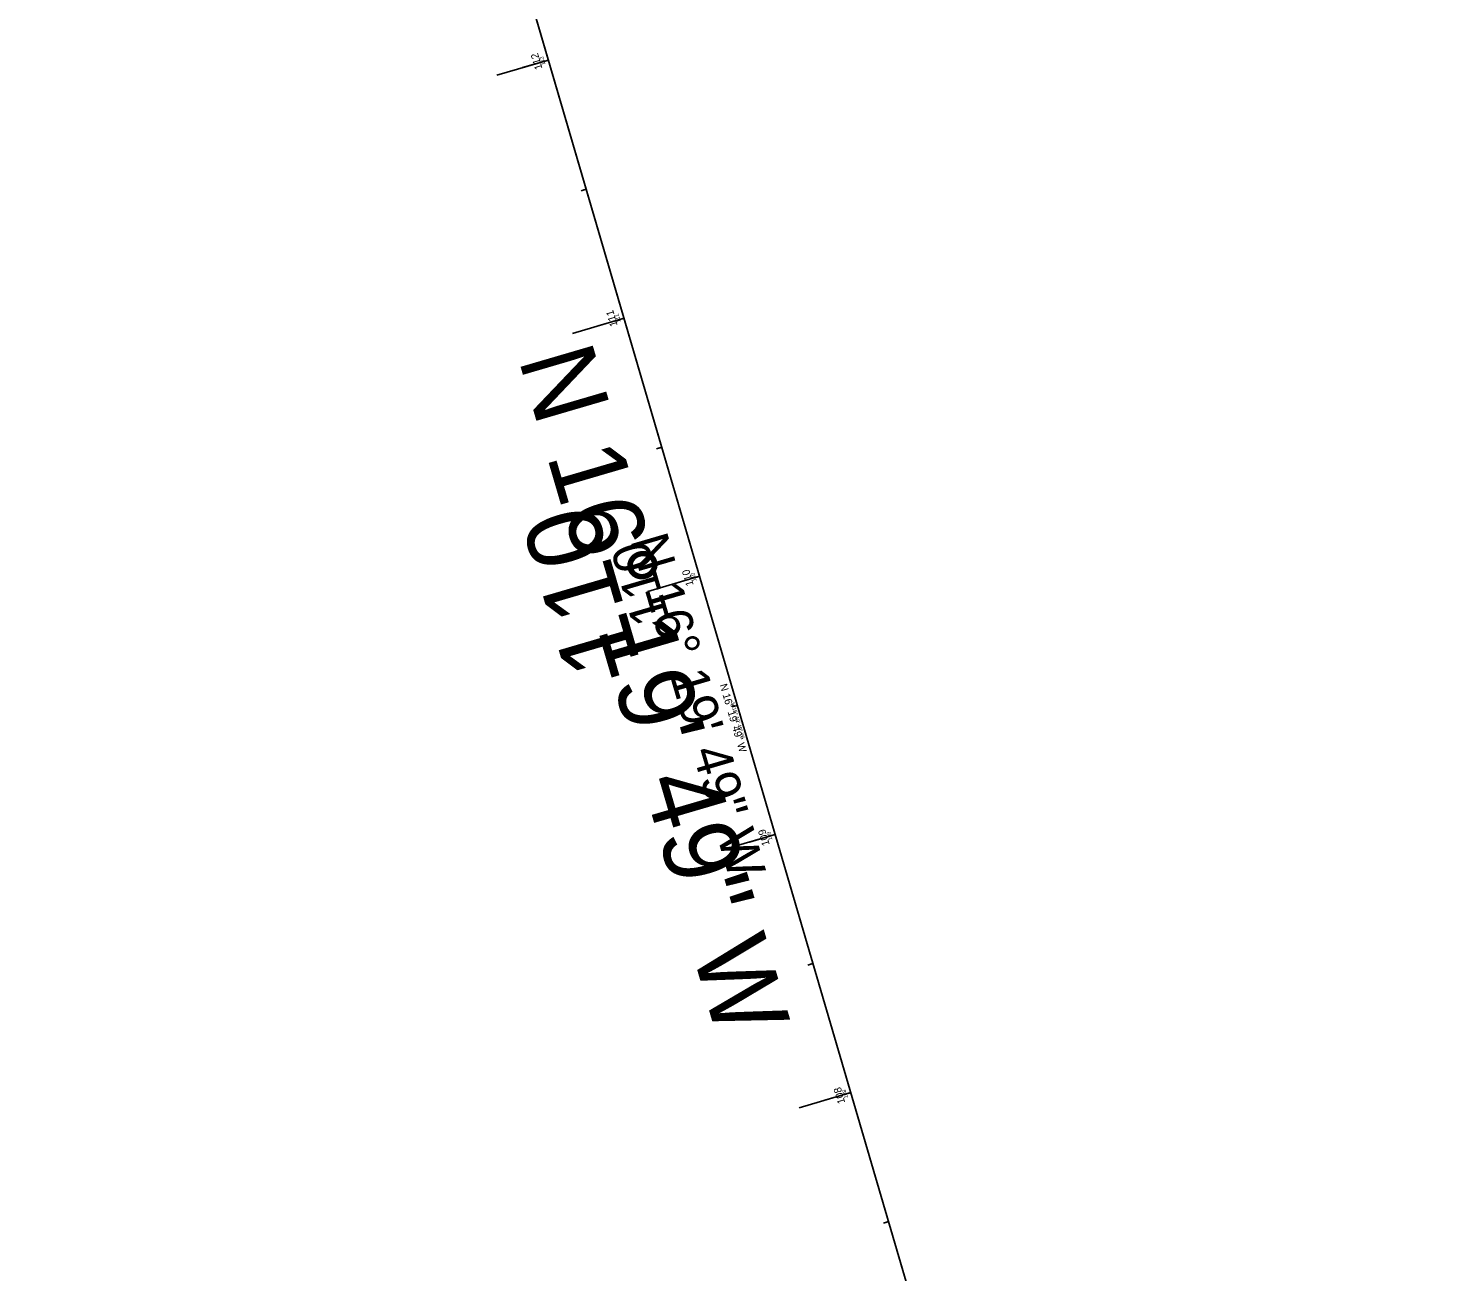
# Model space of a CAD drawing. Extents: x 1794716 to 1797874, y 325521 to 329174.
# Drawn here: x 1796270 to 1796801, y 326414 to 326876 of the extents above; entities that cross this region are included whole.
import ezdxf

# ---------------------------------------------------------------- set-up
doc = ezdxf.new("R2010")
doc.units = 0
for name, color, linetype in [('GE_P_CL_10', 7, 'Continuous'), ('GE_P_CL_100', 7, 'Continuous'), ('GE_P_CL_20', 7, 'Continuous'), ('GE_P_CL_200', 7, 'Continuous'), ('RW_X_CL_20', 7, 'Continuous')]:
    doc.layers.add(name, color=color, linetype=linetype)

msp = doc.modelspace()

# ---------------------------------------------------------------- linework, layer by layer
at = {"layer": 'GE_P_CL_10'}
for p, q in [((1796800.73, 325712.87), (1796269.93, 327524.51)), ((1796463.32, 326864.46), (1796462.36, 326864.18)), ((1796477.38, 326816.48), (1796476.42, 326816.19)), ((1796491.44, 326768.49), (1796490.48, 326768.21)), ((1796505.5, 326720.51), (1796504.54, 326720.23)), ((1796519.56, 326672.53), (1796518.6, 326672.25)), ((1796533.61, 326624.54), (1796532.66, 326624.26)), ((1796547.67, 326576.56), (1796546.71, 326576.28)), ((1796561.73, 326528.58), (1796560.77, 326528.3)), ((1796575.79, 326480.6), (1796574.83, 326480.31)), ((1796589.85, 326432.61), (1796588.89, 326432.33))]:
    msp.add_line(p, q, dxfattribs=at)
at = {"layer": 'GE_P_CL_100'}
for p, q in [((1796800.73, 325712.87), (1796269.93, 327524.51)), ((1796463.32, 326864.46), (1796453.72, 326861.65)), ((1796491.44, 326768.49), (1796481.84, 326765.68)), ((1796519.56, 326672.53), (1796509.96, 326669.72)), ((1796547.67, 326576.56), (1796538.08, 326573.75)), ((1796575.79, 326480.6), (1796566.19, 326477.78))]:
    msp.add_line(p, q, dxfattribs=at)
at = {"layer": 'GE_P_CL_20'}
for p, q in [((1796800.73, 325712.87), (1796269.93, 327524.51)), ((1796463.32, 326864.46), (1796461.4, 326863.9)), ((1796477.38, 326816.48), (1796475.46, 326815.91)), ((1796491.44, 326768.49), (1796489.52, 326767.93)), ((1796505.5, 326720.51), (1796503.58, 326719.95)), ((1796519.56, 326672.53), (1796517.64, 326671.96)), ((1796533.61, 326624.54), (1796531.7, 326623.98)), ((1796547.67, 326576.56), (1796545.75, 326576)), ((1796561.73, 326528.58), (1796559.81, 326528.02)), ((1796575.79, 326480.6), (1796573.87, 326480.03)), ((1796589.85, 326432.61), (1796587.93, 326432.05))]:
    msp.add_line(p, q, dxfattribs=at)
at = {"layer": 'GE_P_CL_200'}
for p, q in [((1796800.73, 325712.87), (1796269.93, 327524.51)), ((1796463.32, 326864.46), (1796444.13, 326858.83)), ((1796491.44, 326768.49), (1796472.25, 326762.87)), ((1796519.56, 326672.53), (1796500.36, 326666.9)), ((1796547.67, 326576.56), (1796528.48, 326570.94)), ((1796575.79, 326480.6), (1796556.6, 326474.97))]:
    msp.add_line(p, q, dxfattribs=at)
at = {"layer": 'RW_X_CL_20'}
msp.add_lwpolyline([(1796800.73, 325712.87), (1796269.93, 327524.51)], dxfattribs=at)

# ---------------------------------------------------------------- texts
at = {"layer": 'GE_P_CL_10'}
for s, rotation, p in [('112', 106.3303, (1796462.21, 326862.9)), ('111', 106.3303, (1796490.27, 326767.16)), ('110', 106.3303, (1796518.46, 326670.94)), ('N 16%%d 19\' 49" W', 286.3303, (1796531.17, 326625.42)), ('109', 106.3303, (1796546.66, 326574.67)), ('108', 106.3303, (1796574.78, 326478.72))]:
    msp.add_text(s, height=1.4, rotation=rotation, dxfattribs=at).set_placement(p)
at = {"layer": 'GE_P_CL_100'}
for s, rotation, p in [('N 16%%d 19\' 49" W', 286.3303, (1796493.72, 326686.03)), ('110', 106.3303, (1796508.58, 326656.63))]:
    msp.add_text(s, height=14, rotation=rotation, dxfattribs=at).set_placement(p)
at = {"layer": 'GE_P_CL_20'}
for s, rotation, p in [('112', 106.3303, (1796461.11, 326861.34)), ('111', 106.3303, (1796489.09, 326765.82)), ('110', 106.3303, (1796517.36, 326669.35)), ('N 16%%d 19\' 49" W', 286.3303, (1796527.01, 326632.16)), ('109', 106.3303, (1796545.66, 326572.78)), ('108', 106.3303, (1796573.76, 326476.85))]:
    msp.add_text(s, height=2.8, rotation=rotation, dxfattribs=at).set_placement(p)
at = {"layer": 'GE_P_CL_200'}
for s, rotation, p in [('N 16%%d 19\' 49" W', 286.3303, (1796452.1, 326753.37)), ('110', 106.3303, (1796497.61, 326640.73))]:
    msp.add_text(s, height=28, rotation=rotation, dxfattribs=at).set_placement(p)

doc.saveas('drawing.dxf')
